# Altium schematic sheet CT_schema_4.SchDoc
size 299 x 185 mm
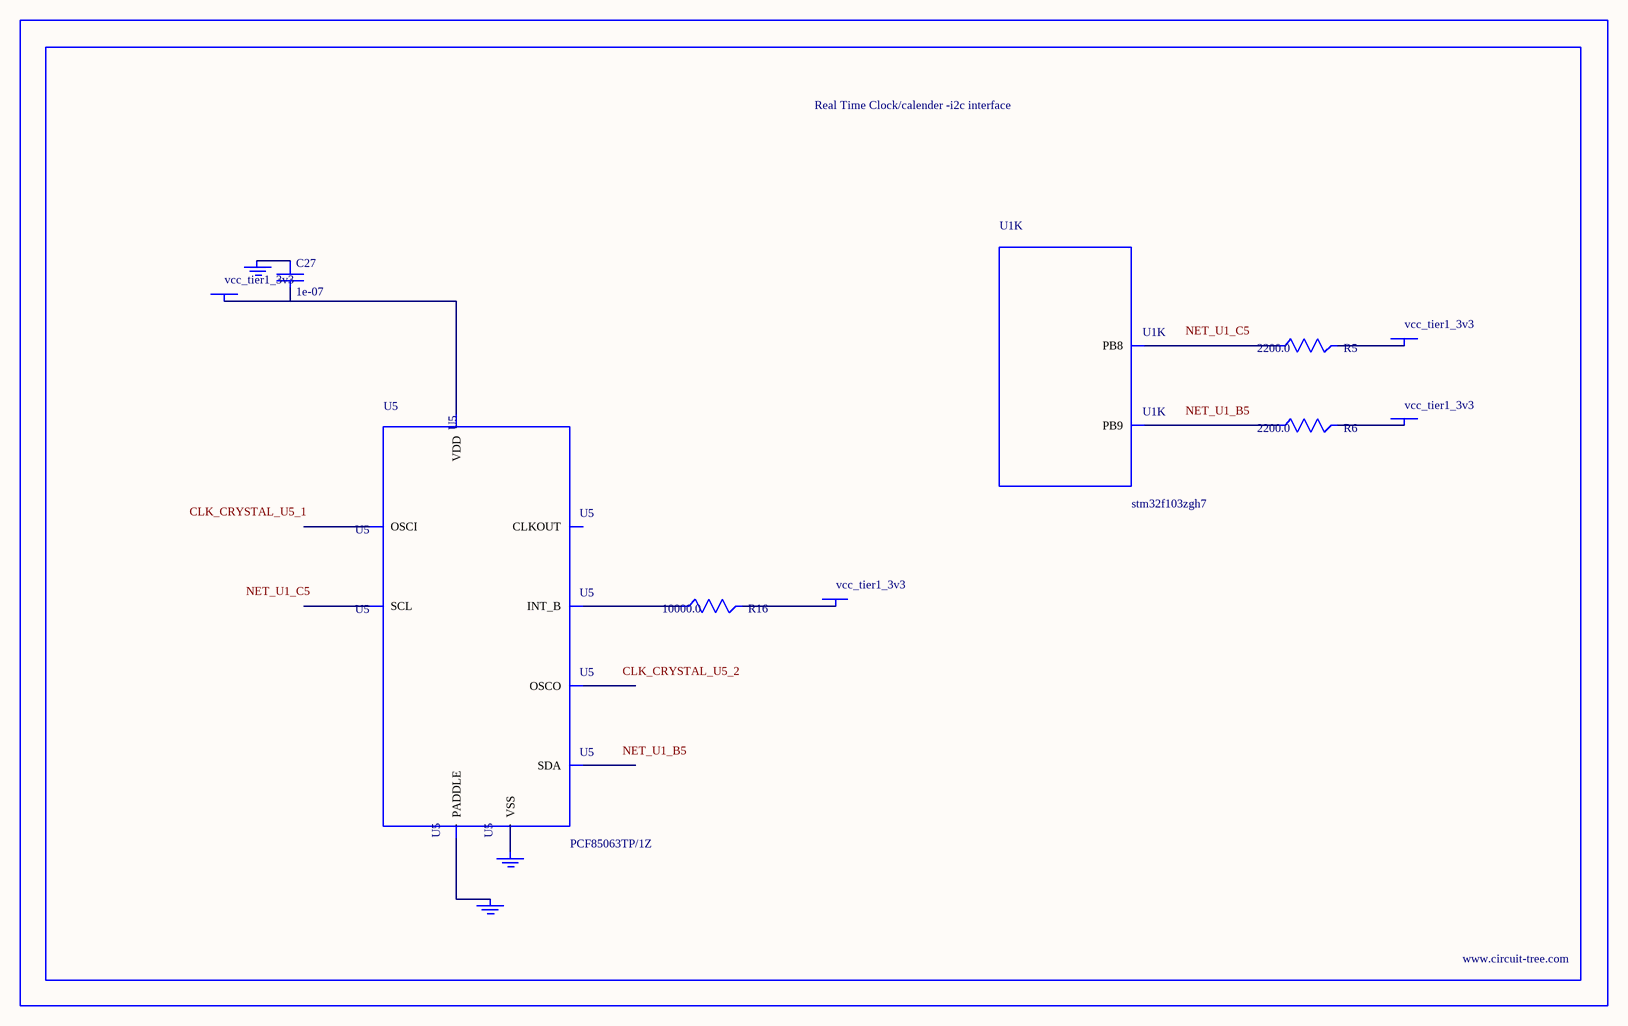
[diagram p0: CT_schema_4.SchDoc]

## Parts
BORDER3  (no value)
C27  1e-07  [C0402]
GND_INSTANCE_3_0  (no value)
GND_INSTANCE_3_1  (no value)
GND_INSTANCE_3_2  (no value)
POWER_INSTANCE_3_0  vcc_tier1_3v3
POWER_INSTANCE_3_1  vcc_tier1_3v3
POWER_INSTANCE_3_2  vcc_tier1_3v3
POWER_INSTANCE_3_3  vcc_tier1_3v3
R5  2200.0  [R0603]
R6  2200.0  [R0603]
R16  10000.0  [R0603]
U1  stm32f103zgh7  [LFBGA144]  (part K of 12)
U5  PCF85063TP/1Z  [SON-8]

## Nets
NetC27_1: C27.1 GND_INSTANCE_3_0.0(GND)
NetC27_2: C27.2 POWER_INSTANCE_3_1.0(PWR) U5.8(VDD)
NetGND_INSTANCE_3_1_0: GND_INSTANCE_3_1.0(GND) U5.PAD(PADDLE)
NetGND_INSTANCE_3_2_0: GND_INSTANCE_3_2.0(GND) U5.4(VSS)
NetPOWER_INSTANCE_3_0_0: POWER_INSTANCE_3_0.0(PWR) R16.2
NetPOWER_INSTANCE_3_2_0: POWER_INSTANCE_3_2.0(PWR) R5.2
NetPOWER_INSTANCE_3_3_0: POWER_INSTANCE_3_3.0(PWR) R6.2
NetR5_1: R5.1 U1.C5(PB8)
NetR6_1: R6.1 U1.B5(PB9)
NetR16_1: R16.1 U5.3(INT_B)

Not connected (* = marked no-connect by the designer): U5 1(OSCI) 2(OSCO) 5(SDA) 6(SCL) 7(CLKOUT)

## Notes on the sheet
- Labels drawn without touching a wire or pin: CLK_CRYSTAL_U5_1, CLK_CRYSTAL_U5_2, NET_U1_B5, NET_U1_C5

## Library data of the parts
BORDER3 = BORDER_PAGE3
C27 = C0402C104K3RACTU
GND_INSTANCE_3_0-GND_INSTANCE_3_2 = GND
POWER_INSTANCE_3_0-POWER_INSTANCE_3_3 = PWR
R5 R6 = RC0603JR-072K2L
R16 = RC0603JR-0710KL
